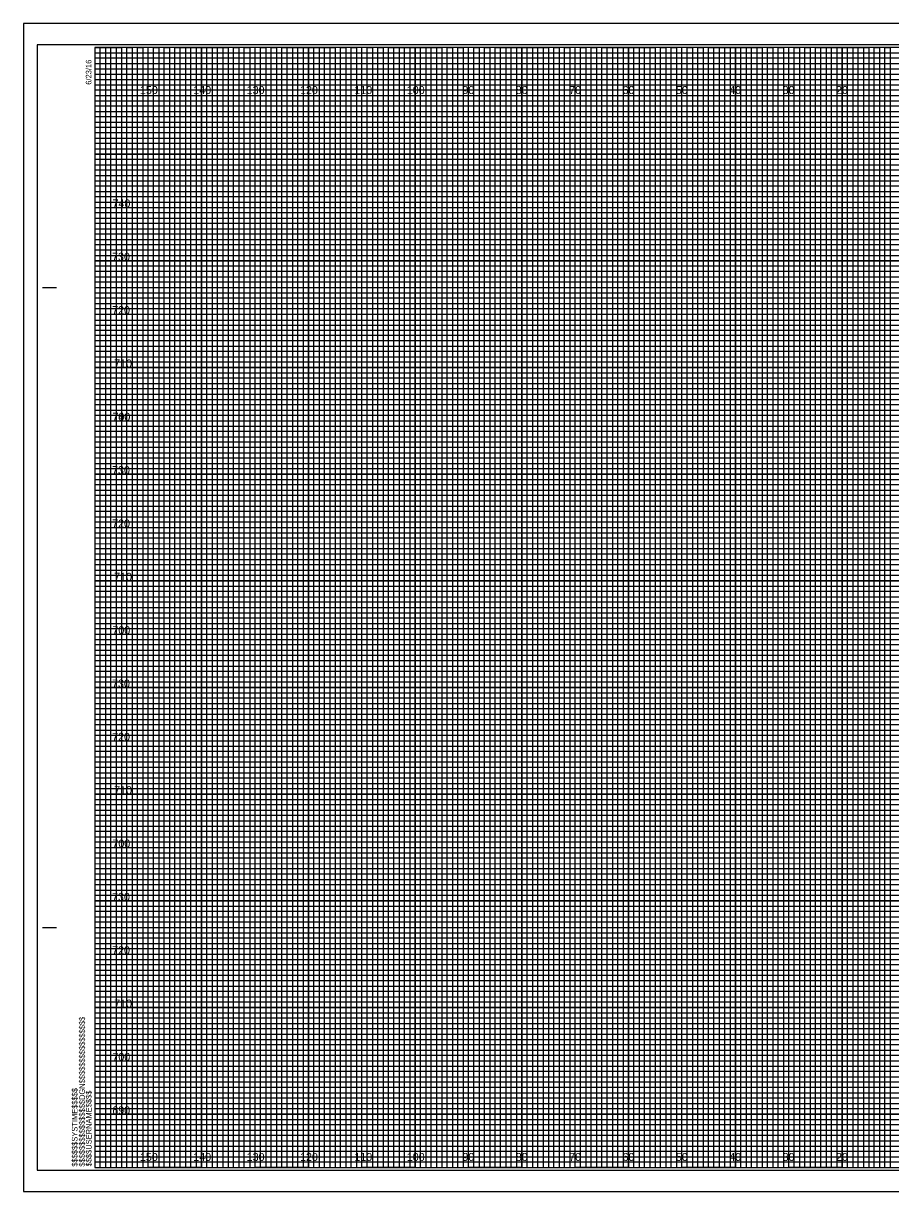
# Model space of a CAD drawing. Extents: x -98 to 717, y -10 to 1974.
# Drawn here: x -13.4 to 149.1, y 655.5 to 874.5 of the extents above; entities that cross this region are included whole.
import ezdxf

# ---------------------------------------------------------------- set-up
doc = ezdxf.new("R2010")
doc.units = 0
for name, color, linetype in [('Default', 7, 'Continuous'), ('Exist XS Center Line Elevation Label', 7, 'Continuous'), ('Prop CMT Conc Surface', 7, 'Continuous'), ('Prop CMT Concrete Structures', 7, 'Continuous'), ('Prop CMT Pvmt Course 1 CG', 7, 'Continuous'), ('Prop CMT Pvmt Course 2', 7, 'Continuous'), ('Prop CMT Pvmt Course 3', 7, 'Continuous'), ('Prop CMT Pvmt Surface', 7, 'Continuous'), ('Prop CMT Subgrade Earthwork', 7, 'Continuous'), ('Prop XS Earthwork Shape', 7, 'Continuous'), ('Prop XS Elevation Labels', 7, 'Continuous'), ('Typical Curb CELL', 7, 'Continuous')]:
    doc.layers.add(name, color=color, linetype=linetype)

msp = doc.modelspace()

# ---------------------------------------------------------------- linework, layer by layer
at = {"layer": 'Default'}
msp.add_lwpolyline([(-13.4, 655.5), (323.3, 655.5), (323.3, 874.5), (-13.4, 874.5)], close=True, dxfattribs=at)
at = {"layer": 'Exist XS Center Line Elevation Label'}
for p, q in [((0, 869), (260, 869)), ((260, 867.98), (0, 867.98)), ((0, 867.98), (0, 867)), ((0, 867), (260, 867)), ((260, 865.89), (0, 865.89)), ((0, 865.89), (0, 864)), ((0, 864), (320, 864))]:
    msp.add_line(p, q, dxfattribs=at)
for points in [[(0, 863), (270, 863), (320, 863), (320, 862), (0, 862)], [(0, 861), (320, 861), (320, 859), (0, 859)], [(0, 858), (320, 858), (320, 857), (0, 856.98)], [(0, 856), (320, 856), (320, 854), (0, 854)], [(0, 853), (320, 853), (320, 852), (0, 852)], [(0, 851), (320, 851), (320, 849), (0, 849)], [(0, 848), (320, 848), (320, 847), (0, 847)], [(0, 846), (320, 846), (320, 844), (0, 844)], [(0, 843), (320, 843), (320, 842), (0, 842)], [(0, 841), (320, 841), (320, 839), (0, 839)], [(0, 838), (320, 838), (320, 837), (0, 837)], [(0, 836), (320, 836), (320, 833.95), (320, 833), (320, 832), (0, 832)], [(0, 834), (320, 834), (320, 833), (0, 833)], [(0, 831), (320, 831), (320, 829), (0, 829.03)], [(0, 829.03), (320, 829), (320, 828), (0, 828)], [(0, 827), (320, 827), (320, 826), (0, 826)], [(0, 824), (320, 824), (320, 823), (0, 823)], [(0, 822), (320, 822), (320, 821), (0, 821)], [(-0.07, 818.89), (320, 818.89), (320, 817.88), (-0.07, 817.88)], [(0, 817), (320, 817), (320, 816), (0, 816)], [(0, 814), (320, 814), (320, 813), (0, 813)], [(0, 812), (320, 812), (320, 811), (0, 811)], [(0, 809), (320, 809), (320, 808), (0, 808)], [(0, 807), (320, 807), (320, 806), (0, 806)], [(0, 804), (320, 804), (320, 803), (0, 803)], [(0, 802), (320, 802), (320, 801), (0, 801)], [(0, 799), (320, 799), (319.99, 797.98), (0, 798)], [(0, 797), (320, 797), (320, 796), (0, 796)], [(0, 794), (320, 794), (320, 793), (0, 793)], [(0, 792), (320, 792), (320, 791), (0, 791)], [(0, 789), (320, 789), (320, 788), (0, 788)], [(0, 787), (320, 787), (320, 786), (0, 786)], [(0, 784), (320, 784), (320, 783), (0, 783)], [(0, 782), (320, 782), (320, 781), (0, 781)], [(0, 779), (320, 779), (320, 778), (0, 778)], [(0, 776.99), (320.07, 776.91), (320, 776), (0, 776)], [(0, 774), (320, 774), (320, 773), (0, 773)], [(0, 772), (320, 772), (320, 771), (0, 771)], [(0, 769), (320, 769), (320, 768), (0, 768)], [(0, 767), (320, 767), (320, 766), (0, 766)], [(0, 764), (320, 764), (320, 763), (0, 763)], [(0, 762), (320, 762), (320, 761), (0, 761)], [(0, 759), (320, 759), (320, 758), (0, 758)], [(0, 757), (320, 757), (320, 756), (0, 756)], [(0, 754), (320, 754), (320, 753), (0, 753)], [(0, 752), (320, 752), (320, 751), (0, 751)], [(0, 749), (320, 749), (320, 748), (0, 748)], [(0, 747), (320, 747), (320, 746), (0, 746)], [(0, 744), (320, 744), (320, 743), (0, 743)], [(0, 742), (320, 742), (320, 741), (0, 741)], [(0, 739), (320, 739), (319.99, 737.98), (0, 738)], [(0, 737), (320, 737), (320, 736), (0, 736)], [(0, 734), (320, 734), (320, 733), (0, 733)], [(0, 732), (320, 732), (320, 731), (0, 731)], [(0, 729), (320, 729), (320, 728), (0, 728)], [(0, 727), (320, 727), (320, 726), (0, 726)], [(0, 724), (320, 724), (320, 723), (0, 723)], [(0, 722), (320, 722), (320, 721), (0, 721)], [(0, 719), (320, 719), (320, 718), (0, 718)], [(0, 716.99), (320.07, 716.91), (320, 716), (0, 716)], [(0, 714), (320, 714), (320, 713), (0, 713)], [(0, 712), (320, 712), (320, 711), (0, 711)], [(0, 709), (320, 709), (320, 708), (0, 708)], [(0, 707), (320, 707), (320, 706), (0, 706)], [(0, 704), (320, 704), (320, 703), (0, 703)], [(0, 702), (320, 702), (320, 701), (0, 701)], [(0, 699), (320, 699), (320, 698), (0, 698)], [(0, 697), (320, 697), (320, 696), (0, 696)], [(0, 694), (320, 694), (320, 693), (0, 693)], [(0, 692), (320, 692), (320, 691), (0, 691)], [(0, 689), (320, 689), (320, 688), (0, 688)], [(0, 687), (320, 687), (320, 686), (0, 686)], [(0, 684), (320, 684), (320, 683), (0, 683)], [(0, 682), (320, 682), (320, 681), (0, 681)], [(0, 679), (320, 679), (320, 678), (0, 678)], [(0, 677), (320, 677), (320, 676), (0, 676)], [(0, 674), (320, 674), (320, 673), (0, 673)], [(0, 672), (320, 672), (320, 671), (0, 671)], [(0, 669), (320, 669), (320, 668), (0, 668)], [(0, 667), (320, 667), (320, 666), (0, 666)], [(0, 664), (320, 664), (320, 663), (0, 663)], [(0, 662), (320, 662), (320, 661), (0, 661)]]:
    msp.add_lwpolyline(points, dxfattribs=at)
at = {"layer": 'Prop CMT Conc Surface'}
for p, q in [((-9.8, 825), (-7.3, 825)), ((-9.7, 825), (-7.2, 825)), ((-9.8, 705), (-7.3, 705)), ((-9.7, 705), (-7.2, 705)), ((0, 660), (0, 660)), ((0, 660), (0, 660)), ((0, 660), (0, 660)), ((0, 660), (0, 660)), ((0, 660), (0, 660)), ((0, 660), (0, 660)), ((0, 660), (0, 660))]:
    msp.add_line(p, q, dxfattribs=at)
msp.add_lwpolyline([(320, 870), (0, 870), (0, 660), (320, 660)], close=True, dxfattribs=at)
at = {"layer": 'Prop CMT Concrete Structures'}
for p, q in [((10, 660), (10, 870)), ((20, 660), (20, 870)), ((30, 660), (30, 870)), ((40, 660), (40, 870)), ((50, 660), (50, 870)), ((60, 660), (60, 870)), ((70, 660), (70, 870)), ((80, 660), (80, 870)), ((90, 660), (90, 870)), ((100, 660), (100, 870)), ((110, 660), (110, 870)), ((120, 660), (120, 870)), ((130, 660), (130, 870)), ((140, 660), (140, 870)), ((0, 860), (320, 860)), ((0, 850), (320, 850)), ((0, 840), (320, 840)), ((0, 830), (320, 830)), ((0, 820), (320, 820)), ((0, 810), (320, 810)), ((0, 800), (320, 800)), ((0, 790), (320, 790)), ((0, 780), (320, 780)), ((0, 770), (320, 770)), ((0, 760), (320, 760)), ((0, 750), (320, 750)), ((0, 740), (320, 740)), ((0, 730), (320, 730)), ((0, 720), (320, 720)), ((0, 710), (320, 710)), ((0, 700), (320, 700)), ((0, 690), (320, 690)), ((0, 680), (320, 680)), ((0, 670), (320, 670))]:
    msp.add_line(p, q, dxfattribs=at)
at = {"layer": 'Prop CMT Pvmt Course 2'}
msp.add_lwpolyline([(-13.4, 655.5), (323.3, 655.5), (323.3, 874.5), (-13.4, 874.5)], close=True, dxfattribs=at)
at = {"layer": 'Prop CMT Pvmt Course 3'}
msp.add_lwpolyline([(-10.8, 659.5), (322.4, 659.5), (322.4, 870.5), (-10.8, 870.5)], close=True, dxfattribs=at)
at = {"layer": 'Prop CMT Pvmt Surface'}
for p, q in [((323.3, 874.5), (-13.4, 874.5)), ((-13.4, 874.5), (-13.4, 655.5)), ((-13.4, 655.5), (323.3, 655.5))]:
    msp.add_line(p, q, dxfattribs=at)
at = {"layer": 'Prop CMT Subgrade Earthwork'}
for points in [[(0, 660), (1, 660), (1, 870), (2, 870), (2, 660)], [(2, 660), (3, 660), (3, 870), (4, 870), (4, 660)], [(5, 660), (6, 660), (6, 870), (7, 870), (7, 660)], [(7, 660), (8, 660), (8, 870), (9, 870), (9, 660)], [(10, 660), (11, 660), (11, 870), (12, 870), (12, 660)], [(12, 660), (13, 660), (13, 870), (14, 870), (14, 660)], [(15, 660), (16, 660), (16, 870), (17, 870), (17, 660)], [(17, 660), (18, 660), (18, 870), (19, 870), (19, 660)], [(20, 660), (21, 660), (21, 870), (22, 870), (22, 660)], [(22, 660), (23, 660), (23, 870), (24, 870), (24, 660)], [(25, 660), (26, 660), (26, 870), (27, 870), (27, 660)], [(27, 660), (28, 660), (28, 870), (29, 870), (29, 660)], [(30, 660), (31, 660), (31, 870), (32, 870), (32, 660)], [(32, 660), (33, 660), (33, 870), (34, 870), (34, 660)], [(35, 660), (36, 660), (36, 870), (37, 870), (37, 660)], [(37, 660), (38, 660), (38, 870), (39, 870), (39, 660)], [(40, 660), (41, 660), (41, 870), (42, 870), (42, 660)], [(42, 660), (43, 660), (43, 870), (44, 870), (44, 660)], [(45, 660), (46, 660), (46, 870), (47, 870), (47, 660)], [(47, 660), (48, 660), (48, 870), (49, 870), (49, 660)], [(50, 660), (51, 660), (51, 870), (52, 870), (52, 660)], [(52, 660), (53, 660), (53, 870), (54, 870), (54, 660)], [(55, 660), (56, 660), (56, 870), (57, 870), (57, 660)], [(57, 660), (58, 660), (58, 870), (59, 870), (59, 660)], [(60, 660), (61, 660), (61, 870), (62, 870), (62, 660)], [(62, 660), (63, 660), (63, 870), (64, 870), (64, 660)], [(65, 660), (66, 660), (66, 870), (67, 870), (67, 660)], [(67, 660), (68, 660), (68, 870), (69, 870), (69, 660)], [(70, 660), (71, 660), (71, 870), (72, 870), (72, 660)], [(72, 660), (73, 660), (73, 870), (74, 870), (74, 660)], [(75, 660), (76, 660), (76, 870), (77, 870), (77, 660)], [(77, 660), (78, 660), (78, 870), (79, 870), (79, 660)], [(80, 660), (81, 660), (81, 870), (82, 870), (82, 660)], [(82, 660), (83, 660), (83, 870), (84, 870), (84, 660)], [(85, 660), (86, 660), (86, 870), (87, 870), (87, 660)], [(87, 660), (88, 660), (88, 870), (89, 870), (89, 660)], [(90, 660), (91, 660), (91, 870), (92, 870), (92, 660)], [(92, 660), (93, 660), (93, 870), (94, 870), (94, 660)], [(95, 660), (96, 660), (96, 870), (97, 870), (97, 660)], [(97, 660), (98, 660), (98, 870), (99, 870), (99, 660)], [(100, 660), (101, 660), (101, 870), (102, 870), (102, 660)], [(102, 660), (103, 660), (103, 870), (104, 870), (104, 660)], [(105, 660), (106, 660), (106, 870), (107, 870), (107, 660)], [(107, 660), (108, 660), (108, 870), (109, 870), (109, 660)], [(110, 660), (111, 660), (111, 870), (112, 870), (112, 660)], [(112, 660), (113, 660), (113, 870), (114, 870), (114, 660)], [(115, 660), (116, 660), (116, 870), (117, 870), (117, 660)], [(117, 660), (118, 660), (118, 870), (119, 870), (119, 660)], [(120, 660), (121, 660), (121, 870), (122, 870), (122, 660)], [(122, 660), (123, 660), (123, 870), (124, 870), (124, 660)], [(125, 660), (126, 660), (126, 870), (127, 870), (127, 660)], [(127, 660), (128, 660), (128, 870), (129, 870), (129, 660)], [(130, 660), (131, 660), (131, 870), (132, 870), (132, 660)], [(132, 660), (133, 660), (133, 870), (134, 870), (134, 660)], [(135, 660), (136, 660), (136, 870), (137, 870), (137, 660)], [(137, 660), (138, 660), (138, 870), (139, 870), (139, 660)], [(140, 660), (141, 660), (141, 870), (142, 870), (142, 660)], [(142, 660), (143, 660), (143, 870), (144, 870), (144, 660)], [(145, 660), (146, 660), (146, 870), (147, 870), (147, 660)], [(147, 660), (148, 660), (148, 870), (149, 870), (149, 660)]]:
    msp.add_lwpolyline(points, dxfattribs=at)
at = {"layer": 'Prop XS Elevation Labels'}
for p, q in [((10, 870), (0, 870)), ((10, 660), (10, 870)), ((30, 870), (20, 870)), ((20, 870), (20, 660)), ((30, 660), (30, 870)), ((50, 870), (40, 870)), ((40, 870), (40, 660)), ((50, 660), (50, 870)), ((70, 870), (60, 870)), ((60, 870), (60, 660)), ((70, 660), (70, 870)), ((90, 870), (80, 870)), ((80, 870), (80, 660)), ((90, 660), (90, 870)), ((110, 870), (100, 870)), ((100, 870), (100, 660)), ((110, 660), (110, 870)), ((130, 870), (120, 870)), ((120, 870), (120, 660)), ((130, 660), (130, 870)), ((150, 870), (140, 870)), ((140, 870), (140, 660)), ((20, 660), (10, 660)), ((40, 660), (30, 660)), ((60, 660), (50, 660)), ((80, 660), (70, 660)), ((100, 660), (90, 660)), ((120, 660), (110, 660)), ((140, 660), (130, 660))]:
    msp.add_line(p, q, dxfattribs=at)
for points in [[(0, 860), (320, 860), (320, 850), (0, 850)], [(0, 840), (320, 840), (320, 830), (0, 830)], [(0, 820), (320, 820), (320, 810), (0, 810)], [(0, 800), (320, 800), (320, 790), (0, 790)], [(0, 780), (320, 780), (320, 770), (0, 770)], [(0, 760), (320, 760), (320, 750), (0, 750)], [(0, 740), (320, 740), (320, 730), (0, 730)], [(0, 720), (320, 720), (320, 710), (0, 710)], [(0, 700), (320, 700), (320, 690), (0, 690)], [(0, 680), (320, 680), (320, 670), (0, 670)]]:
    msp.add_lwpolyline(points, dxfattribs=at)
at = {"layer": 'Typical Curb CELL'}
for points in [[(0, 870), (5, 870), (5, 660), (15, 660), (15, 870), (25, 870), (25, 660), (35, 660), (35, 870), (45, 870), (45, 660), (55, 660), (55, 870), (65, 870), (65, 660), (75, 660), (75, 870), (85, 870), (85, 660), (95, 660), (95, 870), (105, 870), (105, 660), (115, 660), (115, 870), (125, 870), (125, 660), (135, 660), (135, 870), (145, 870), (145, 660), (155, 660)], [(0, 865), (275, 865)], [(0, 845), (320, 845), (320, 855), (0, 855)], [(0, 825), (320, 825), (320, 835), (0, 835)], [(0, 805), (320, 805), (320, 815), (0, 815)], [(0, 785), (320, 785), (320, 795), (0, 795)], [(0, 765), (320, 765), (320, 775), (0, 775)], [(0, 745), (320, 745), (320, 755), (0, 755)], [(0, 725), (320, 725), (320, 735), (0, 735)], [(0, 705), (320, 705), (320, 715), (0, 715)], [(0, 685), (320, 685), (320, 695), (0, 695)], [(0, 665), (320, 665), (320, 675), (0, 675)]]:
    msp.add_lwpolyline(points, dxfattribs=at)

# ---------------------------------------------------------------- texts
at = {"layer": 'Prop CMT Conc Surface'}
for s, p in [('6/23/16', (-0.65, 863)), ('$$$$$$$$$$$$$$$$DGN$$$$$$$$$$$$$$$$', (-1.88, 660.18)), ('$$$$$$SYSTIME$$$$$', (-3.26, 660.18)), ('$$$$USERNAME$$$$', (-0.62, 660.23))]:
    msp.add_text(s, height=1.05, rotation=90, dxfattribs=at).set_placement(p)
at = {"layer": 'Prop CMT Pvmt Course 1 CG'}
for s, p in [('740', (3.3, 840)), ('730', (3.22, 830)), ('720', (3.23, 820)), ('710', (3.61, 810)), ('700', (3.28, 800)), ('740', (3.3, 800)), ('730', (3.22, 790)), ('720', (3.23, 780)), ('710', (3.61, 770)), ('700', (3.28, 760)), ('730', (3.22, 750)), ('720', (3.23, 740)), ('710', (3.61, 730)), ('700', (3.28, 720)), ('730', (3.22, 710)), ('720', (3.23, 700)), ('710', (3.61, 690)), ('700', (3.28, 680)), ('690', (3.26, 670))]:
    msp.add_text(s, height=1.5, dxfattribs=at).set_placement(p)
at = {"layer": 'Prop XS Earthwork Shape'}
for s, p in [('150', (8.44, 861.25)), ('140', (18.44, 861.25)), ('130', (28.44, 861.25)), ('120', (38.44, 861.25)), ('110', (48.62, 861.25)), ('100', (58.44, 861.25)), ('90', (68.86, 861.25)), ('80', (78.86, 861.25)), ('70', (88.86, 861.25)), ('60', (98.86, 861.25)), ('50', (108.86, 861.25)), ('40', (118.86, 861.25)), ('30', (128.86, 861.25)), ('20', (138.86, 861.25)), ('150', (8.44, 661.25)), ('140', (18.44, 661.25)), ('130', (28.44, 661.25)), ('120', (38.44, 661.25)), ('110', (48.62, 661.25)), ('100', (58.44, 661.25)), ('90', (68.86, 661.25)), ('80', (78.86, 661.25)), ('70', (88.86, 661.25)), ('60', (98.86, 661.25)), ('50', (108.86, 661.25)), ('40', (118.86, 661.25)), ('30', (128.86, 661.25)), ('20', (138.86, 661.25))]:
    msp.add_text(s, height=1.5, dxfattribs=at).set_placement(p)

doc.saveas('drawing.dxf')
